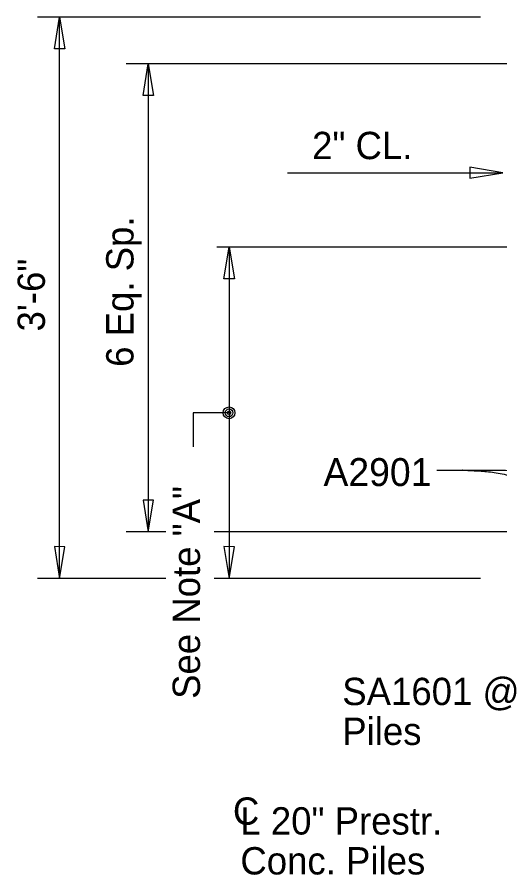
# Model space of a CAD drawing. Extents: x 437 to 537, y 571 to 720.
# Drawn here: x 501.39 to 507.46, y 669.62 to 680.41 of the extents above; entities that cross this region are included whole.
import ezdxf

# ---------------------------------------------------------------- set-up
doc = ezdxf.new("R2010")
doc.units = 0
for name, color, linetype in [('BR_AUTO DIMENSION', 7, 'Continuous'), ('BR_TEXT', 7, 'Continuous'), ('Default', 7, 'Continuous')]:
    doc.layers.add(name, color=color, linetype=linetype)

msp = doc.modelspace()

# ---------------------------------------------------------------- linework, layer by layer
at = {"layer": 'BR_AUTO DIMENSION'}
for p, q in [((501.86, 680.007), (501.926, 680.406)), ((501.926, 680.406), (501.993, 680.007)), ((501.993, 680.007), (501.86, 680.007)), ((502.975, 679.421), (503.041, 679.82)), ((503.041, 679.82), (503.108, 679.421)), ((503.108, 679.421), (502.975, 679.421)), ((507.499, 678.449), (507.086, 678.518)), ((507.086, 678.518), (507.086, 678.38)), ((507.086, 678.38), (507.499, 678.449)), ((503.991, 677.114), (504.057, 677.513)), ((504.057, 677.513), (504.124, 677.114)), ((504.124, 677.114), (503.991, 677.114)), ((504.079, 675.43), (503.605, 675.43)), ((503.605, 675.43), (503.605, 675.004)), ((506.668, 674.71), (506.993, 674.71)), ((503.108, 674.332), (502.975, 674.333)), ((502.975, 674.333), (503.041, 673.934)), ((503.041, 673.934), (503.108, 674.332)), ((501.993, 673.746), (501.86, 673.747)), ((501.86, 673.747), (501.926, 673.348)), ((501.926, 673.348), (501.993, 673.746)), ((504.124, 673.746), (503.991, 673.747)), ((503.991, 673.747), (504.057, 673.348)), ((504.057, 673.348), (504.124, 673.746))]:
    msp.add_line(p, q, dxfattribs=at)
at = {"layer": 'Default'}
for p, q in [((507.22, 680.406), (501.648, 680.406)), ((501.926, 673.348), (501.926, 680.406)), ((507.745, 679.82), (502.762, 679.82)), ((503.041, 679.82), (503.041, 673.934)), ((504.79, 678.449), (507.499, 678.449)), ((508.799, 677.513), (503.901, 677.513)), ((504.057, 677.513), (504.057, 673.348)), ((503.26, 673.934), (502.762, 673.934)), ((507.745, 673.934), (503.869, 673.934)), ((503.26, 673.348), (501.648, 673.348)), ((507.22, 673.348), (503.869, 673.348))]:
    msp.add_line(p, q, dxfattribs=at)
for radius in [0.0741, 0.0486, 0.022]:
    msp.add_circle((504.057, 675.43), radius, dxfattribs=at)
for points in [[(506.993, 674.71), (506.993, 674.71), (506.993, 674.71), (508.174, 674.702), (508.576, 674.407), (508.945, 674.01), (508.945, 674.01)], [(506.993, 674.71), (506.993, 674.71), (506.993, 674.71), (507.431, 674.686), (507.926, 674.547), (508.163, 674.036), (508.163, 674.036)]]:
    msp.add_open_spline(points, degree=2, dxfattribs=at)

# ---------------------------------------------------------------- texts
at = {"layer": 'BR_TEXT'}
for s, height, p in [('2" CL.', 0.3438, (505.101, 678.62)), ('A2901', 0.3511, (505.244, 674.509)), ('SA1601 @', 0.3438, (505.48, 671.754)), ('Piles', 0.3438, (505.48, 671.253)), ('C', 0.344, (504.105, 670.249)), ('L 20" Prestr. ', 0.34375, (504.199, 670.126)), ('Conc. Piles', 0.34375, (504.199, 669.624))]:
    msp.add_text(s, height=height, dxfattribs=at).set_placement(p)
for s, height, p in [('6 Eq. Sp.', 0.3438, (502.855, 676.008)), ('3\'-6"', 0.3438, (501.741, 676.453)), ('See Note "A"', 0.34375, (503.691, 671.832))]:
    msp.add_text(s, height=height, rotation=90, dxfattribs=at).set_placement(p)

doc.saveas('drawing.dxf')
